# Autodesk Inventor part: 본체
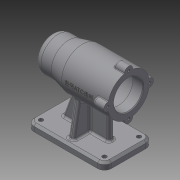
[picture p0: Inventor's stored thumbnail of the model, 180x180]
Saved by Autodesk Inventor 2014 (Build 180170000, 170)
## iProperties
Created: 2019-07
Part Number: 본체
Material: Generic
Document SubType Name: Modeling
Designer: kh
Density: 1 g/cm^3
Appearance: Default
Author: kh
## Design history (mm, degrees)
sketch "Sketch1"
  geometry: C1 r 30 at (0, 0); 1 further point
  constraints: 1 centre point, 1 coincident
  dimensions: "d0" = 60 diameter of C1
extrude "Extrusion1" new body sketch "Sketch1" distance "d1" = 67; taper "d2" = 0 deg
sketch "Sketch2"
  geometry: L1 (0, 0)-(-112, 0); L2 (-112, 25)-(-87, 25); L3 (0, 30)-(-67, 30) reference; L4 (-67, 30)-(-87, 25); L5 (-112, 25)-(-112, 0); L6 (-67, 30)-(-67, 0)
  constraints: 10 end point, 1 horizontal, 1 parallel, 1 perpendicular, 1 point on line
  dimensions: "d3" = 112 distance of L1.start L1.end; "d4" = 50 diameter of L2 L1; "d5" = 25 distance of L2.start L2.end; "d6" = 45 horizontal distance of L3.end L2.start
revolve "Revolution1" sketch "Sketch2" stored, may be unused: angle "d7" = 90 deg
workplane "Work Plane1"
sketch "Sketch4"
  geometry: L1 (112, 35)-(0, 35); L2 (0, 35)-(0, -35); L3 (0, -35)-(112, -35); L4 (112, -35)-(112, 35); L5 (112, 35)-(0, -35); L6 (0, 35)-(112, -35); 3 further points
  constraints: 12 end point, 3 midpoint, 2 parallel, 1 horizontal, 1 horizontal alignment, 1 perpendicular, 1 vertical alignment
  dimensions: "d10" = 112 distance of L1.start L1.end; "d11" = 70 distance of L1.end L2.end
extrude "Extrusion2" join sketch "Sketch4" distance "d12" = 10; taper "d13" = 0 deg
fillet "Fillet2" dims "d14" = 10
chamfer "Chamfer1" distance "d16" = 3; stored, may be unused: second distance "d17" = 2, angle "d18" = 45 deg
sketch "Sketch5"
  geometry: C1 r 6 at (0, 30); 2 further points
  constraints: 2 vertical alignment, 1 centre point, 1 other
  dimensions: "d55" = 12 diameter of C1
extrude "Extrusion3" join sketch "Sketch5" distance "d56" = 16; taper "d57" = 0 deg
hole "Hole5" diameter "d60" = 3.242; stored, may be unused: countersink angle "d64" = 90 deg, drill point angle "d66" = 118 deg; dims "d58" = 10, "d59" = 10, "d61" = 8, "d62" = 4, "d63" = 2, "d65" = 11
pattern_circular "Circular Pattern1" dims angle "d68" = 360 deg
fillet "Fillet4" dims "d70" = 3
fillet "Fillet5" dims "d71" = 1
sketch "Sketch8"
  geometry: L1 (-92, -70)-(-67.25, -2); L2 (-67.25, -2)-(-25, -2); L3 (-25, -2)-(-25, -70); L4 (-92, -70)-(-25, -70); L5 (-112, -80)-(-112, -73) reference; L6 (-109, -70)-(-102, -70) reference; L7 (0, -73)-(0, -80) reference; 1 further point
  constraints: 8 end point, 2 horizontal, 1 collinear, 1 perpendicular
  dimensions: "d99" = 110 deg angle of L1 L6; "d100" = 20 distance from line of L1.start L5; "d101" = 25 distance from line of L7 L3.end; "d102" = 68 distance between parallel lines of L4 L2
extrude "Extrusion4" join sketch "Sketch8" stored distance "d103" = 8; taper "d104" = 0 deg
sketch "Sketch6"
  geometry: L1 (0, 0)-(-112, 0); L2 (0, 0)-(0, 21); L3 (0, 21)-(-15, 21); L4 (-15, 21)-(-15, 24); L5 (-15, 24)-(-69, 24); L6 (-69, 24)-(-69, 21); L7 (-69, 21)-(-81, 21); L8 (-81, 21)-(-81, 17.5); L9 (-81, 17.5)-(-99, 17.5); L10 (-99, 17.5)-(-99, 16); L11 (-99, 16)-(-103, 16); L12 (-103, 16)-(-103, 10.5); L13 (-103, 10.5)-(-106, 10.5); L14 (-106, 10.5)-(-106, 0)
  constraints: 28 end point, 8 parallel, 3 perpendicular, 1 collinear, 1 horizontal, 1 point on line, 1 vertical
  dimensions: "d72" = 112 distance of L1.start L1.end; "d73" = 42 diameter of L3 L1; "d74" = 15 distance of L2.end L3.end; "d75" = 54 distance of L4.end L5.end; "d76" = 48 diameter of L5 L1; "d77" = 42 diameter of L7 L1; "d78" = 12 distance of L6.end L7.end; "d79" = 18 distance of L8.end L9.end; "d80" = 4 distance of L10.end L11.end; "d81" = 3 distance of L12.end L13.end; "d82" = 35 diameter of L9 L1; "d83" = 32 diameter of L11 L1; "d84" = 21 diameter of L13 L1
revolve "Revolution2" sketch "Sketch6" stored, may be unused: angle "d85" = 90 deg
fillet "Fillet6" dims "d86" = 3
fillet "Fillet7" dims "d87" = 0.3
workplane "Work Plane2"
sketch "Sketch10"
  geometry: L1 (-3, 10)-(5.346, 57.334); L2 (-7, 10)-(0, 10) reference; L3 (-10, 0)-(-10, 7) reference; A1 r 30 centre (25, 80) between (-4.226, 73.229) and (18.229, 50.774) reference; 1 further point
  constraints: 2 end point, 1 point on circle, 1 point on line
  dimensions: "d105" = 100 deg angle of L1 L2; "d106" = 7 distance from line of L1.start L3
feature "Rib1" sketch "Sketch10" dims "d107" = 1, "d108" = 8, "d109" = 0, "d110" = 0, "d111" = 1, "d112" = 1
mirror "Mirror1"
fillet "Fillet8" dims "d113" = 3
fillet "Fillet9" dims "d114" = 3
hole "Hole6" diameter "d120" = 6; stored, may be unused: countersink angle "d124" = 90 deg, drill point angle "d126" = 118 deg; dims "d118" = 10, "d119" = 10, "d121" = 8, "d122" = 4, "d123" = 2, "d125" = 11
pattern_linear "Rectangular Pattern1"
chamfer "Chamfer2" distance "d131" = 1; stored, may be unused: second distance "d132" = 2, angle "d133" = 45 deg
workplane "Work Plane3"
sketch "Sketch12"
  geometry: L1 (0, 5.998)-(0, -5.998) reference; 3 further points
  constraints: 1 horizontal alignment, 1 midpoint, 1 other
  dimensions: "d134" = 42 distance from line of point (-42, 0) L1
emboss "Emboss1" sketch "Sketch12" dims "d12" = 10, "d13" = 0, "d135" = 0.5, "d136" = 0
body "Solid1"
